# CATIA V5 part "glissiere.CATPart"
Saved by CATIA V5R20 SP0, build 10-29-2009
Part number: glissiere
Bounding box of the stored display mesh (mm): x 0 to 4, y -24.962 to -20.962, z -40.025 to -6.025
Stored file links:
  D:\IAO\22janv\glissiere.CATPart
  D:\IAO\22janv\czortea.CATProduct
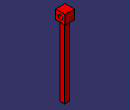
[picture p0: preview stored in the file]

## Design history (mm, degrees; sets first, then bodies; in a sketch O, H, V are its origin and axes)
External parameters (linked from other documents)
  External.epaisseur = 2 mm
  External.L = 50 mm
Set1
  Sketch1 on yz-plane, origin (0, 0, 0), H (0, 1, 0), V (0, 0, 1)
    line L1 (-24.9625, -6.0248) -> (-20.9625, -6.0248)
    line L2 (-20.9625, -6.0248) -> (-20.9625, -10.0248)
    line L3 (-20.9625, -10.0248) -> (-24.9625, -10.0248)
    line L4 (-24.9625, -10.0248) -> (-24.9625, -6.0248)
    length L1 = 4 {= External.epaisseur *2}
    length L2 = 4 {= External.epaisseur *2}
    horizontal: L1 H, L3 H
    vertical: L2 V, L4 V
Body1 (main body)
  Pad1: profile Sketch1, direction (1, 0, 0), length 4 {= External.epaisseur *2}
  Sketch2 on end face of Pad1, origin (4, -22.6821, -7.6095), H (0, 1, 0), V (0, 0, 1)
    point P1 (-0.2804, -0.4153)
    reference projected line E1 (1.7196, 1.5847) -> (-2.2804, 1.5847) from edge [face of Pad1 from Sketch1.L1 | end face of Pad1]
    reference projected line E2 (-2.2804, 1.5847) -> (-2.2804, -2.4153) from edge [face of Pad1 from Sketch1.L4 | end face of Pad1]
    distance P1 E1 = 2 {= External.epaisseur}
    distance P1 E2 = 2 {= External.epaisseur}
  Hole1: placed by Sketch2, at (4, -22.9625, -8.0248) direction (-1, 0, 0), diameter 2 {= External.epaisseur}, through (limit type 6)
  Sketch3 on face of Pad1 from Sketch1.L3, origin (0, 0, -10.0248), H (1, 0, 0), V (0, -1, 0)
    point P1 (1, 23.9625)
    line L1 (1, 23.9625) -> (3.2061, 23.9625)
    line L2 (3.2061, 23.9625) -> (3.2061, 21.9625)
    line L3 (3.2061, 21.9625) -> (1, 21.9625)
    line L4 (1, 21.9625) -> (1, 23.9625)
    point P2 (3.2061, 23.9625)
    reference projected line E1 (0, 20.9625) -> (4, 20.9625) from edge [face of Pad1 from Sketch1.L2 | face of Pad1 from Sketch1.L3]
    reference projected line E2 (0, 24.9625) -> (4, 24.9625) from edge [face of Pad1 from Sketch1.L3 | face of Pad1 from Sketch1.L4]
    reference projected line E3 (4, 24.9625) -> (4, 20.9625) from edge [face of Pad1 from Sketch1.L3 | end face of Pad1]
    reference projected line E4 (0, 24.9625) -> (0, 20.9625) from edge [start face of Pad1 | face of Pad1 from Sketch1.L3]
    distance L3 E1 = 1 {= External.epaisseur /2}
    distance L1 E2 = 1 {= External.epaisseur /2}
    distance P2 E3 = 0.7939
    distance P1 E4 = 1 {= External.epaisseur /2}
    horizontal: L1 H, L3 H
    vertical: L2 V, L4 V
  Pad2: profile Sketch3, direction (0, 0, -1), length 30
